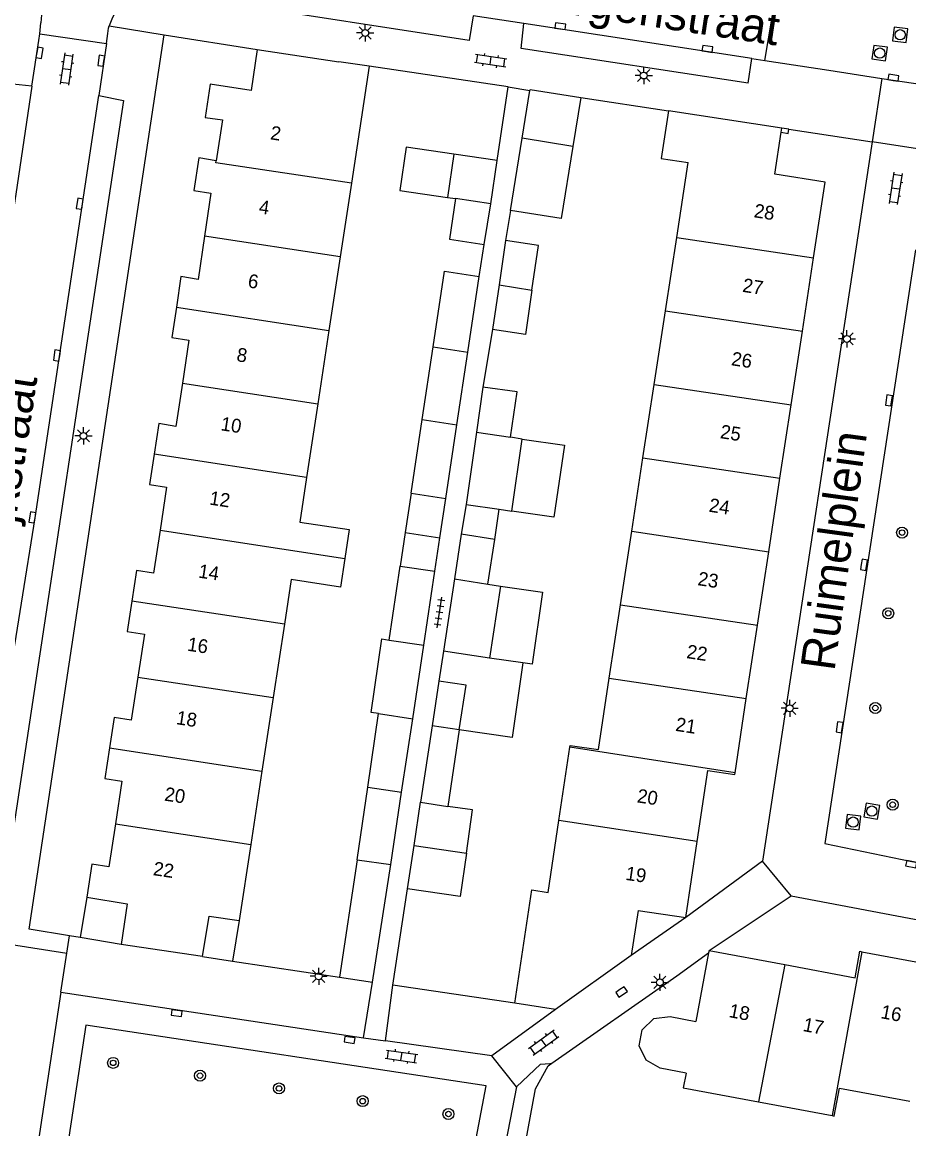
# Model space of a CAD drawing. Extents: x 124000 to 128010, y 398999 to 403000.
# Drawn here: x 126590.7 to 126655.1, y 399713.9 to 399794.3 of the extents above; entities that cross this region are included whole.
import ezdxf

# ---------------------------------------------------------------- set-up
doc = ezdxf.new("R2010")
doc.units = 0
for name, color, linetype in [('gg-afsc-erfafscheiding', 7, 'Continuous'), ('gg-afsc-muur', 7, 'Continuous'), ('gg-anno-huisnummerreeks BGT', 7, 'Continuous'), ('gg-anno-openbare ruimte label', 7, 'Continuous'), ('gg-bbg-bijgebouw', 7, 'Continuous'), ('gg-bbg-gedigitaliseerde bijgebouw', 7, 'Continuous'), ('gg-bbg-hoofdgebouw', 7, 'Continuous'), ('gg-bbg-luifel en loopbrug', 7, 'Continuous'), ('gg-bbg-tussenscheiding', 7, 'Continuous'), ('gg-knt-verharding', 7, 'Continuous'), ('gg-knt-verharding nz', 7, 'Continuous'), ('gt-grn-weggrens', 7, 'Continuous'), ('gt-symb-boom', 7, 'Continuous'), ('gt-symb-klinker verharding', 7, 'Continuous'), ('gt-symb-kolk', 7, 'Continuous'), ('gt-symb-lichtmast', 7, 'Continuous'), ('gt-symb-rioolschacht', 7, 'Continuous'), ('gt-symb-tegel verharding', 7, 'Continuous')]:
    doc.layers.add(name, color=color, linetype=linetype)

# ---------------------------------------------------------------- blocks, each defined once
blk = doc.blocks.new('gt0-RS')
at = {"layer": 'gt-symb-rioolschacht'}
blk.add_lwpolyline([(-0.5, -0.5), (0.5, -0.5), (0.5, 0.5), (-0.5, 0.5)], close=True, dxfattribs=at)
blk.add_circle((0, 0), 0.375, dxfattribs=at)
blk = doc.blocks.new('gt0-KOLK')
at = {"layer": 'gt-symb-kolk'}
blk.add_lwpolyline([(0, 0), (0.375, 0), (0.375, 0.4), (-0.375, 0.4), (-0.375, 0), (0, 0)], dxfattribs=at)
blk = doc.blocks.new('gt0-KL1')
at = {"layer": 'gt-symb-klinker verharding'}
for p, q in [((-1.15, 0.3), (1.15, 0.3)), ((-1, -0.3), (-1, 0.3)), ((-0.5, 0.3), (-0.5, 0.45)), ((0, -0.3), (0, 0.3)), ((0.5, 0.3), (0.5, 0.45)), ((1, -0.3), (1, 0.3)), ((-1.15, -0.3), (1.15, -0.3)), ((-0.5, -0.45), (-0.5, -0.3)), ((0.5, -0.45), (0.5, -0.3))]:
    blk.add_line(p, q, dxfattribs=at)
blk = doc.blocks.new('gt0-LMAST')
at = {"layer": 'gt-symb-lichtmast'}
for p, q in [((-0.182, 0.173), (-0.447, 0.438)), ((-0.005, 0.246), (-0.005, 0.621)), ((0.172, 0.173), (0.437, 0.438)), ((-0.255, -0.004), (-0.63, -0.004)), ((-0.182, -0.181), (-0.447, -0.446)), ((-0.005, -0.254), (-0.005, -0.629)), ((0.437, -0.446), (0.172, -0.181)), ((0.245, -0.004), (0.62, -0.004))]:
    blk.add_line(p, q, dxfattribs=at)
blk.add_circle((-0.005, -0.004), 0.25, dxfattribs=at)
blk = doc.blocks.new('gt0-BOOM')
at = {"layer": 'gt-symb-boom'}
for radius in [0.4, 0.2]:
    blk.add_circle((0, 0), radius, dxfattribs=at)
blk = doc.blocks.new('gt0-TEG1')
at = {"layer": 'gt-symb-tegel verharding'}
for p, q in [((-1.125, 0), (1.125, 0)), ((-0.9, -0.25), (-0.9, 0.25)), ((-0.45, -0.25), (-0.45, 0.25)), ((0, -0.25), (0, 0.25)), ((0.45, -0.25), (0.45, 0.25)), ((0.9, -0.25), (0.9, 0.25))]:
    blk.add_line(p, q, dxfattribs=at)

msp = doc.modelspace()

# ---------------------------------------------------------------- linework, layer by layer
at = {"layer": 'gg-afsc-erfafscheiding'}
for p, q in [((126626.144, 399780.622), (126625.787, 399778.432)), ((126624.828, 399771.956), (126624.143, 399767.782)), ((126629.145, 399718.635), (126638.226, 399724.997))]:
    msp.add_line(p, q, dxfattribs=at)
msp.add_lwpolyline([(126626.495, 399708.888), (126627.958, 399716.771), (126628.884, 399718.452), (126629.145, 399718.635)], dxfattribs=at)
at = {"layer": 'gg-afsc-muur'}
for p, q in [((126625.967, 399789.6), (126615.878, 399791.089)), ((126625.184, 399784.252), (126625.967, 399789.6)), ((126631.249, 399788.825), (126637.613, 399787.853)), ((126646.369, 399786.516), (126645.849, 399786.603)), ((126623.874, 399775.824), (126624.241, 399778.14)), ((126617.602, 399724.298), (126618.658, 399731.303)), ((126605.957, 399726.055), (126613.712, 399724.885)), ((126626.462, 399722.992), (126617.602, 399724.298))]:
    msp.add_line(p, q, dxfattribs=at)
msp.add_lwpolyline([(126645.804, 399786.294), (126646.307, 399786.196), (126646.369, 399786.516)], dxfattribs=at)
at = {"layer": 'gg-bbg-bijgebouw'}
for p, q in [((126624.241, 399778.14), (126624.721, 399781.086)), ((126625.787, 399778.432), (126625.308, 399775.198)), ((126623.043, 399770.324), (126623.874, 399775.824)), ((126625.308, 399775.198), (126624.828, 399771.956)), ((126622.244, 399765.035), (126623.043, 399770.324)), ((126624.143, 399767.782), (126623.672, 399764.509)), ((126621.434, 399759.677), (126622.244, 399765.035)), ((126623.672, 399764.509), (126622.912, 399759.245)), ((126621.004, 399756.83), (126621.434, 399759.677)), ((126622.557, 399757.081), (126622.064, 399753.833)), ((126619.837, 399749.015), (126620.646, 399754.406)), ((126622.064, 399753.833), (126621.269, 399748.587)), ((126619.036, 399743.675), (126619.837, 399749.015)), ((126620.932, 399746.405), (126620.444, 399743.164)), ((126618.234, 399738.325), (126619.036, 399743.675)), ((126620.444, 399743.164), (126619.608, 399737.603)), ((126617.445, 399733.068), (126618.234, 399738.325)), ((126619.608, 399737.603), (126621.586, 399737.305)), ((126616.116, 399724.522), (126617.445, 399733.068))]:
    msp.add_line(p, q, dxfattribs=at)
msp.add_lwpolyline([(126627.558, 399789.344), (126627.569, 399789.41), (126631.249, 399788.825)], dxfattribs=at)
at = {"layer": 'gg-bbg-gedigitaliseerde bijgebouw'}
for p, q in [((126626.994, 399785.866), (126627.558, 399789.344)), ((126631.249, 399788.825), (126630.673, 399785.269)), ((126630.673, 399785.269), (126626.994, 399785.866)), ((126622.018, 399784.716), (126621.555, 399781.549)), ((126625.184, 399784.252), (126622.018, 399784.716)), ((126624.721, 399781.086), (126625.184, 399784.252)), ((126621.555, 399781.549), (126622.151, 399781.474)), ((126619.724, 399765.414), (126620.525, 399770.713)), ((126618.915, 399760.058), (126619.724, 399765.414)), ((126626.993, 399763.994), (126626.146, 399764.126)), ((126626.239, 399758.765), (126626.993, 399763.994)), ((126618.915, 399760.058), (126618.485, 399757.211)), ((126622.912, 399759.245), (126625.312, 399758.899)), ((126625.312, 399758.899), (126626.239, 399758.765)), ((126618.485, 399757.211), (126621.004, 399756.83)), ((126624.997, 399756.711), (126622.557, 399757.081)), ((126624.503, 399753.454), (126624.997, 399756.711)), ((126617.335, 399749.393), (126618.117, 399754.773)), ((126618.117, 399754.773), (126620.646, 399754.406)), ((126624.503, 399753.454), (126625.412, 399753.313)), ((126625.412, 399753.313), (126624.619, 399748.079)), ((126624.619, 399748.079), (126621.269, 399748.587)), ((126615.781, 399738.697), (126616.559, 399744.051)), ((126622.421, 399742.856), (126621.586, 399737.305)), ((126615.015, 399733.421), (126615.781, 399738.697)), ((126618.658, 399731.303), (126619.134, 399734.457)), ((126619.134, 399734.457), (126622.94, 399733.909)), ((126615.015, 399733.421), (126613.712, 399724.885)), ((126613.712, 399724.885), (126616.116, 399724.522))]:
    msp.add_line(p, q, dxfattribs=at)
for points in [[(126622.151, 399781.474), (126621.705, 399778.523), (126624.241, 399778.14)], [(126627.701, 399774.826), (126628.183, 399778.077), (126625.787, 399778.432)], [(126620.525, 399770.713), (126621.355, 399776.205), (126623.874, 399775.824)], [(126627.701, 399774.826), (126627.224, 399771.601), (126624.828, 399771.956)], [(126626.146, 399764.126), (126626.622, 399767.425), (126624.143, 399767.782)], [(126616.559, 399744.051), (126616.015, 399744.13), (126616.791, 399749.472), (126617.335, 399749.393)], [(126622.421, 399742.856), (126622.91, 399746.107), (126620.932, 399746.405)], [(126622.94, 399733.909), (126622.485, 399730.752), (126618.658, 399731.303)]]:
    msp.add_lwpolyline(points, dxfattribs=at)
at = {"layer": 'gg-bbg-hoofdgebouw'}
for p, q in [((126607.741, 399792.322), (126613.675, 399791.423)), ((126615.878, 399791.089), (126613.675, 399791.423)), ((126615.878, 399791.089), (126614.582, 399782.591)), ((126645.849, 399786.603), (126637.613, 399787.853)), ((126645.804, 399786.294), (126645.849, 399786.603)), ((126638.217, 399778.657), (126639.048, 399784.096)), ((126614.582, 399782.591), (126613.767, 399777.242)), ((126637.401, 399773.32), (126638.217, 399778.657)), ((126613.767, 399777.242), (126612.95, 399771.884)), ((126647.347, 399771.829), (126648.162, 399777.169)), ((126636.583, 399767.972), (126637.401, 399773.32)), ((126612.95, 399771.884), (126612.137, 399766.556)), ((126646.533, 399766.492), (126647.347, 399771.829)), ((126635.767, 399762.634), (126636.583, 399767.972)), ((126612.137, 399766.556), (126611.322, 399761.208)), ((126645.718, 399761.154), (126646.533, 399766.492)), ((126634.952, 399757.306), (126635.767, 399762.634)), ((126644.902, 399755.806), (126645.718, 399761.154)), ((126634.135, 399751.958), (126634.952, 399757.306)), ((126644.089, 399750.476), (126644.902, 399755.806)), ((126633.317, 399746.61), (126634.135, 399751.958)), ((126609.715, 399750.543), (126608.9, 399745.204)), ((126643.275, 399745.138), (126644.089, 399750.476)), ((126608.9, 399745.204), (126608.085, 399739.867)), ((126642.453, 399739.751), (126643.275, 399745.138)), ((126629.665, 399736.278), (126630.459, 399741.607)), ((126608.085, 399739.867), (126607.271, 399734.528)), ((126628.887, 399731.052), (126629.665, 399736.278)), ((126607.271, 399734.528), (126606.429, 399729.013)), ((126638.876, 399729.223), (126639.701, 399734.76)), ((126635.421, 399729.738), (126634.918, 399726.461)), ((126635.421, 399729.738), (126638.876, 399729.223)), ((126603.777, 399726.384), (126597.866, 399727.276)), ((126640.571, 399726.833), (126640.538, 399726.658)), ((126640.571, 399726.833), (126646.068, 399725.8)), ((126634.918, 399726.461), (126629.417, 399722.536)), ((126640.538, 399726.658), (126639.6, 399721.667)), ((126651.67, 399726.743), (126657.031, 399725.737)), ((126629.417, 399722.536), (126626.462, 399722.992)), ((126644.17, 399715.829), (126649.513, 399714.825))]:
    msp.add_line(p, q, dxfattribs=at)
for points in [[(126607.741, 399792.322), (126607.298, 399789.342), (126604.322, 399789.789), (126603.966, 399787.377), (126605.212, 399787.193), (126604.766, 399784.232)], [(126637.613, 399787.853), (126637.088, 399784.393), (126639.048, 399784.096)], [(126648.162, 399777.169), (126649, 399782.665), (126645.355, 399783.242), (126645.804, 399786.294)], [(126604.766, 399784.232), (126603.501, 399784.44), (126603.136, 399782.057), (126604.381, 399781.866), (126603.918, 399778.735)], [(126603.918, 399778.735), (126603.456, 399775.606), (126602.201, 399775.821), (126601.867, 399773.597)], [(126601.867, 399773.597), (126601.532, 399771.373), (126602.778, 399771.186), (126602.303, 399768.055)], [(126602.303, 399768.055), (126601.828, 399764.924), (126600.584, 399765.129), (126600.244, 399762.91)], [(126600.244, 399762.91), (126599.905, 399760.692), (126601.151, 399760.501), (126600.682, 399757.38)], [(126611.322, 399761.208), (126610.828, 399757.969), (126614.423, 399757.428), (126614.106, 399755.326)], [(126600.682, 399757.38), (126600.214, 399754.261), (126598.963, 399754.445), (126598.629, 399752.228)], [(126614.106, 399755.326), (126613.792, 399753.24), (126610.211, 399753.795), (126609.715, 399750.543)], [(126598.629, 399752.228), (126598.295, 399750.013), (126599.541, 399749.825), (126599.068, 399746.694)], [(126599.068, 399746.694), (126598.594, 399743.562), (126597.341, 399743.767), (126597.004, 399741.549)], [(126630.459, 399741.607), (126630.478, 399741.736), (126632.525, 399741.431), (126633.317, 399746.61)], [(126597.004, 399741.549), (126596.667, 399739.332), (126597.913, 399739.143), (126597.44, 399736.024)], [(126639.701, 399734.76), (126640.468, 399739.914), (126642.432, 399739.613), (126642.453, 399739.751)], [(126597.44, 399736.024), (126596.966, 399732.905), (126595.72, 399733.095), (126595.354, 399730.701)], [(126626.462, 399722.992), (126627.694, 399731.231), (126628.887, 399731.052)], [(126595.354, 399730.701), (126598.303, 399730.23), (126597.866, 399727.276)], [(126603.777, 399726.384), (126604.244, 399729.324), (126606.429, 399729.013)], [(126646.068, 399725.8), (126651.188, 399724.837), (126651.532, 399726.769), (126651.67, 399726.743)], [(126638.896, 399717.92), (126637.016, 399718.288), (126635.996, 399718.851), (126635.494, 399719.911), (126635.719, 399721.066), (126636.568, 399721.876), (126637.735, 399722.025), (126639.6, 399721.667)], [(126638.896, 399717.92), (126638.696, 399716.858), (126644.17, 399715.829)], [(126649.513, 399714.825), (126649.654, 399714.798), (126650.036, 399716.832), (126655.152, 399715.875)]]:
    msp.add_lwpolyline(points, dxfattribs=at)
at = {"layer": 'gg-bbg-luifel en loopbrug'}
for p, q in [((126626.144, 399780.622), (126626.994, 399785.866)), ((126622.912, 399759.245), (126622.557, 399757.081)), ((126624.997, 399756.711), (126625.312, 399758.899)), ((126618.485, 399757.211), (126618.117, 399754.773)), ((126620.646, 399754.406), (126621.004, 399756.83)), ((126621.269, 399748.587), (126620.932, 399746.405)), ((126627.035, 399747.731), (126624.619, 399748.079)), ((126619.134, 399734.457), (126619.608, 399737.603)), ((126595.354, 399730.701), (126594.885, 399727.766)), ((126606.429, 399729.013), (126605.957, 399726.055)), ((126597.866, 399727.276), (126594.885, 399727.766)), ((126603.777, 399726.384), (126605.957, 399726.055))]:
    msp.add_line(p, q, dxfattribs=at)
for points in [[(126622.018, 399784.716), (126618.555, 399785.222), (126618.092, 399782.056), (126621.555, 399781.549)], [(126630.673, 399785.269), (126629.822, 399780.025), (126626.144, 399780.622)], [(126626.993, 399763.994), (126630.057, 399763.552), (126629.303, 399758.323), (126626.239, 399758.765)], [(126625.412, 399753.313), (126628.476, 399752.871), (126627.721, 399747.632), (126627.035, 399747.731)], [(126627.035, 399747.731), (126626.252, 399742.304), (126622.421, 399742.856)], [(126622.94, 399733.909), (126623.393, 399737.044), (126621.586, 399737.305)]]:
    msp.add_lwpolyline(points, dxfattribs=at)
at = {"layer": 'gg-bbg-tussenscheiding'}
for p, q in [((126624.721, 399781.086), (126622.151, 399781.474)), ((126613.767, 399777.242), (126603.918, 399778.735)), ((126638.217, 399778.657), (126648.162, 399777.169)), ((126625.308, 399775.198), (126627.701, 399774.826)), ((126601.867, 399773.597), (126612.95, 399771.884)), ((126637.401, 399773.32), (126647.347, 399771.829)), ((126620.525, 399770.713), (126623.043, 399770.324)), ((126602.303, 399768.055), (126612.137, 399766.556)), ((126636.583, 399767.972), (126646.533, 399766.492)), ((126619.724, 399765.414), (126622.244, 399765.035)), ((126623.672, 399764.509), (126626.146, 399764.126)), ((126611.322, 399761.208), (126600.244, 399762.91)), ((126635.767, 399762.634), (126645.718, 399761.154)), ((126618.915, 399760.058), (126621.434, 399759.677)), ((126600.682, 399757.38), (126614.106, 399755.326)), ((126634.952, 399757.306), (126644.902, 399755.806)), ((126622.064, 399753.833), (126624.503, 399753.454)), ((126609.715, 399750.543), (126598.629, 399752.228)), ((126634.135, 399751.958), (126644.089, 399750.476)), ((126617.335, 399749.393), (126619.837, 399749.015)), ((126599.068, 399746.694), (126608.9, 399745.204)), ((126633.317, 399746.61), (126643.275, 399745.138)), ((126616.559, 399744.051), (126619.036, 399743.675)), ((126622.421, 399742.856), (126620.444, 399743.164)), ((126597.004, 399741.549), (126608.085, 399739.867)), ((126642.453, 399739.751), (126630.459, 399741.607)), ((126615.781, 399738.697), (126618.234, 399738.325)), ((126597.44, 399736.024), (126607.271, 399734.528)), ((126639.701, 399734.76), (126629.665, 399736.278)), ((126615.015, 399733.421), (126617.445, 399733.068)), ((126651.67, 399726.743), (126649.513, 399714.825)), ((126646.068, 399725.8), (126644.17, 399715.829))]:
    msp.add_line(p, q, dxfattribs=at)
msp.add_lwpolyline([(126614.582, 399782.591), (126604.742, 399784.074), (126604.766, 399784.232)], dxfattribs=at)
at = {"layer": 'gg-knt-verharding'}
for p, q in [((126644.631, 399791.515), (126645.443, 399796.408)), ((126627.12, 399794.203), (126623.42, 399794.769)), ((126591.178, 399728.376), (126600.983, 399793.367)), ((126591.937, 399793.453), (126596.785, 399792.745)), ((126596.785, 399792.745), (126596.233, 399788.962)), ((126600.983, 399793.367), (126607.741, 399792.322)), ((126643.41, 399789.86), (126643.686, 399791.659)), ((126643.686, 399791.659), (126644.631, 399791.515)), ((126625.967, 399789.6), (126627.558, 399789.344)), ((126646.369, 399786.516), (126652.418, 399785.594)), ((126652.418, 399785.594), (126644.442, 399733.328)), ((126644.442, 399733.328), (126638.876, 399729.223)), ((126640.571, 399726.833), (126646.535, 399730.794)), ((126646.535, 399730.794), (126698.263, 399721.061)), ((126638.876, 399729.223), (126634.918, 399726.461)), ((126594.107, 399727.894), (126591.178, 399728.376)), ((126593.915, 399726.646), (126594.107, 399727.894)), ((126594.885, 399727.766), (126594.107, 399727.894)), ((126593.474, 399723.792), (126593.915, 399726.646)), ((126638.226, 399724.997), (126640.538, 399726.658)), ((126615.465, 399720.491), (126616.116, 399724.522)), ((126593.474, 399723.792), (126615.465, 399720.491)), ((126617.051, 399720.262), (126617.602, 399724.298)), ((126629.417, 399722.536), (126624.785, 399719.176)), ((126615.465, 399720.491), (126617.051, 399720.262)), ((126624.785, 399719.176), (126617.051, 399720.262)), ((126628.332, 399718.558), (126626.572, 399716.912)), ((126628.332, 399718.558), (126628.989, 399718.62)), ((126628.989, 399718.62), (126629.145, 399718.635)), ((126626.572, 399716.912), (126625.068, 399709.196))]:
    msp.add_line(p, q, dxfattribs=at)
for points in [[(126623.42, 399794.769), (126623.139, 399792.96), (126605.536, 399795.683), (126605.759, 399797.472)], [(126643.41, 399789.86), (126626.91, 399792.38), (126627.12, 399794.203)], [(126591.356, 399789.638), (126591.88, 399792.966), (126591.937, 399793.453)], [(126591.356, 399789.638), (126589.539, 399789.847), (126583.635, 399750.863), (126585.43, 399750.479)], [(126596.233, 399788.962), (126598.037, 399788.614), (126589.808, 399734.285), (126587.988, 399734.591)], [(126655.557, 399777.762), (126648.977, 399734.6), (126655.293, 399733.299), (126668.247, 399731), (126690.456, 399726.808)], [(126591.062, 399693.474), (126618.92, 399688.259), (126624.371, 399717.004), (126595.282, 399721.391), (126591.062, 399693.474)]]:
    msp.add_lwpolyline(points, dxfattribs=at)
at = {"layer": 'gg-knt-verharding nz'}
for p, q in [((126592.078, 399794.824), (126592.03, 399794.248)), ((126591.937, 399793.453), (126592.03, 399794.248)), ((126643.686, 399791.659), (126627.12, 399794.203)), ((126596.785, 399792.745), (126596.89, 399793.466)), ((126644.631, 399791.515), (126649.267, 399790.805)), ((126649.267, 399790.805), (126653.125, 399790.214)), ((126653.125, 399790.214), (126661.06, 399788.999)), ((126590.98, 399727.103), (126593.915, 399726.646))]:
    msp.add_line(p, q, dxfattribs=at)
for points in [[(126596.89, 399793.466), (126596.937, 399793.866), (126596.985, 399794.021)], [(126591.356, 399789.638), (126590.197, 399781.808), (126585.43, 399750.479)], [(126587.988, 399734.591), (126589.633, 399745.863), (126591.601, 399758.278), (126596.233, 399788.962)], [(126588.82, 399724.493), (126589.263, 399727.371), (126590.98, 399727.103)], [(126593.474, 399723.792), (126588.931, 399693.795), (126584.204, 399694.491)]]:
    msp.add_lwpolyline(points, dxfattribs=at)
msp.add_arc((126602.358, 399792.282), 5.647, 78.92851, 162.06538, dxfattribs=at)
at = {"layer": 'gt-grn-weggrens'}
for p, q in [((126596.985, 399794.021), (126600.983, 399793.367)), ((126653.125, 399790.214), (126652.418, 399785.594)), ((126656.667, 399784.937), (126652.418, 399785.594)), ((126646.535, 399730.794), (126644.442, 399733.328)), ((126626.572, 399716.912), (126624.785, 399719.176))]:
    msp.add_line(p, q, dxfattribs=at)

# ---------------------------------------------------------------- block references
at = {"layer": 'gt-symb-boom'}
for p in [(126654.593, 399757.201), (126653.585, 399751.338), (126652.648, 399744.454), (126653.905, 399737.422), (126597.276, 399718.66), (126603.587, 399717.733), (126609.329, 399716.804), (126615.406, 399715.88), (126621.635, 399714.944)]:
    msp.add_blockref('gt0-BOOM', p, dxfattribs=at)
at = {"layer": 'gt-symb-klinker verharding'}
for p, rotation in [((126593.896, 399790.89), -98.27589282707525), ((126624.705, 399791.508), -8.45426172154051), ((126654.116, 399782.22), -98.68085058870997), ((126628.556, 399720.149), 35.930518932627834), ((126618.229, 399719.131), -8.219209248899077)]:
    msp.add_blockref('gt0-KL1', p, dxfattribs=dict(at, rotation=rotation))
at = {"layer": 'gt-symb-kolk'}
for p, rotation in [((126629.738, 399793.81), -8.219209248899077), ((126591.73, 399792.101), -99.84862238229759), ((126640.417, 399792.159), -9.207969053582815), ((126596.607, 399791.464), 81.31914941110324), ((126653.932, 399790.065), -8.567589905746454), ((126595.046, 399781.074), 81.48906580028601), ((126593.39, 399770.042), 81.37577126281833), ((126653.435, 399766.834), -98.80280445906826), ((126591.601, 399758.278), 80.97080115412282), ((126651.628, 399754.889), -98.68085058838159), ((126649.849, 399743.087), -98.62422873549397), ((126655.293, 399733.299), 168.3415983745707), ((126634.098, 399723.987), -146.54839854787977), ((126601.918, 399722.472), 173.4509084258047), ((126614.478, 399720.531), 171.60242742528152)]:
    msp.add_blockref('gt0-KOLK', p, dxfattribs=dict(at, rotation=rotation))
at = {"layer": 'gt-symb-lichtmast'}
for p in [(126615.593, 399793.519), (126635.828, 399790.426), (126650.591, 399771.283), (126595.126, 399764.236), (126646.432, 399744.437), (126612.215, 399724.959), (126636.999, 399724.514)]:
    msp.add_blockref('gt0-LMAST', p, dxfattribs=at)
at = {"layer": 'gt-symb-rioolschacht'}
for p, rotation in [((126654.457, 399793.38), 82.87498365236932), ((126652.965, 399792.049), 81.9509382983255), ((126652.391, 399736.959), 80.20785375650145), ((126651.027, 399736.16), 82.93185994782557)]:
    msp.add_blockref('gt0-RS', p, dxfattribs=dict(at, rotation=rotation))
at = {"layer": 'gt-symb-tegel verharding', "rotation": 81.25383773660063}
msp.add_blockref('gt0-TEG1', (126620.983, 399751.398), dxfattribs=at)

# ---------------------------------------------------------------- texts
at = {"layer": 'gg-anno-huisnummerreeks BGT'}
for s, rotation, p in [('2', 351.4, (126608.653, 399785.788)), ('4', 351.6, (126607.816, 399780.405)), ('28', 351.3, (126643.781, 399780.126)), ('6', 351.6, (126607.021, 399775.024)), ('27', 351.3, (126642.954, 399774.705)), ('8', 351.4, (126606.2, 399769.664)), ('26', 351.3, (126642.14, 399769.37)), ('10', 351.4, (126605.045, 399764.643)), ('25', 351.3, (126641.331, 399764.069)), ('12', 351.4, (126604.222, 399759.243)), ('24', 351.3, (126640.515, 399758.725)), ('14', 351.5, (126603.425, 399753.934)), ('23', 351.3, (126639.701, 399753.386)), ('16', 351.4, (126602.62, 399748.624)), ('22', 351.3, (126638.892, 399748.085)), ('18', 351.4, (126601.812, 399743.283)), ('21', 351.3, (126638.086, 399742.796)), ('20', 351.4, (126600.958, 399737.727)), ('20', 351.5, (126635.294, 399737.599)), ('22', 351.4, (126600.136, 399732.311)), ('19', 351.5, (126634.455, 399731.967)), ('18', 349.3, (126641.958, 399721.995)), ('16', 349.4, (126652.989, 399721.917)), ('17', 349.3, (126647.337, 399720.983))]:
    msp.add_text(s, height=1, rotation=rotation, dxfattribs=at).set_placement(p)
at = {"layer": 'gg-anno-openbare ruimte label'}
for s, rotation, p in [('Rijsbergenstraat', 351.4, (126621.408, 399796.238)), ('Randwijkstraat', 81.4, (126588.493, 399746.783)), ('Ruimelplein', 82.2, (126649.676, 399747.084))]:
    msp.add_text(s, height=2.5, rotation=rotation, dxfattribs=at).set_placement(p)

doc.saveas('drawing.dxf')
